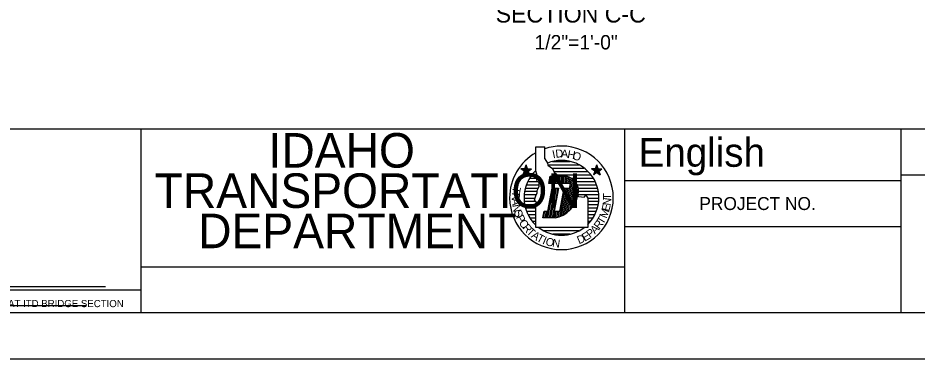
# Model space of a CAD drawing. Extents: x 0 to 68, y 0 to 47.1.
# Drawn here: x 25.33 to 44.86, y 0 to 7.4 of the extents above; entities that cross this region are included whole.
import ezdxf

# ---------------------------------------------------------------- set-up
doc = ezdxf.new("R2010")
doc.units = 0
for name, color, linetype in [('BORDER_ANNO_Cutsheet', 7, 'Continuous'), ('BRDG_ANNO_Anno-Large-Print', 7, 'Continuous'), ('BRDG_ANNO_Anno-Sheet', 7, 'Continuous'), ('BRDG_ANNO_Anno-Small-Print', 7, 'Continuous'), ('BRDG_ANNO_General-Notes', 7, 'Continuous')]:
    doc.layers.add(name, color=color, linetype=linetype)

msp = doc.modelspace()

# ---------------------------------------------------------------- linework, layer by layer
at = {"layer": 'BORDER_ANNO_Cutsheet'}
msp.add_lwpolyline([(0, 44), (68, 44), (68, 0), (0, 0)], close=True, dxfattribs=at)
at = {"layer": 'BRDG_ANNO_Anno-Large-Print'}
msp.add_line((23.799, 1.161), (26.811, 1.161), dxfattribs=at)
at = {"layer": 'BRDG_ANNO_Anno-Sheet'}
for p, q in [((3, 5), (38.5, 5)), ((28, 1), (28, 5)), ((38.5, 1), (38.5, 5)), ((38.5, 5), (67, 5)), ((44.5, 1), (44.5, 5)), ((36.569, 4.085), (36.569, 4.606)), ((36.569, 4.606), (36.766, 4.606)), ((36.766, 4.346), (36.766, 4.606)), ((36.766, 4.346), (36.819, 4.252)), ((36.402, 4.08), (36.245, 4.131)), ((36.331, 4.131), (36.245, 4.131)), ((36.315, 4.08), (36.245, 4.131)), ((36.386, 4.131), (36.288, 3.996)), ((36.315, 4.08), (36.474, 4.131)), ((36.331, 4.131), (36.359, 4.214)), ((36.331, 4.131), (36.43, 3.996)), ((36.359, 4.047), (36.359, 4.214)), ((36.386, 4.131), (36.359, 4.214)), ((36.386, 4.131), (36.474, 4.131)), ((36.402, 4.08), (36.474, 4.131)), ((36.819, 4.252), (36.829, 4.21)), ((36.829, 4.21), (36.932, 4.138)), ((36.834, 4.216), (37.501, 4.216)), ((36.93, 4.289), (37.316, 4.289)), ((36.93, 4.145), (37.614, 4.145)), ((36.932, 4.138), (36.965, 4.054)), ((37.935, 4.08), (37.776, 4.131)), ((37.847, 4.08), (37.776, 4.131)), ((37.864, 4.131), (37.776, 4.131)), ((37.919, 4.131), (37.82, 3.996)), ((37.847, 4.08), (38.005, 4.131)), ((37.864, 4.131), (37.891, 4.214)), ((37.864, 4.131), (37.962, 3.996)), ((37.891, 4.047), (37.891, 4.214)), ((37.919, 4.131), (37.891, 4.214)), ((37.919, 4.131), (38.005, 4.131)), ((37.935, 4.08), (38.005, 4.131)), ((36.315, 4.08), (36.288, 3.996)), ((36.359, 4.047), (36.288, 3.996)), ((36.359, 4.047), (36.43, 3.996)), ((36.402, 4.08), (36.43, 3.996)), ((36.434, 3.929), (36.585, 3.929)), ((36.484, 4.001), (36.587, 4.001)), ((36.549, 4.072), (36.572, 4.072)), ((36.589, 4.013), (36.569, 4.085)), ((36.589, 3.95), (36.589, 4.013)), ((36.589, 3.897), (36.589, 3.95)), ((36.85, 3.814), (36.881, 3.971)), ((36.879, 3.814), (36.907, 3.971)), ((36.881, 3.971), (37.225, 3.971)), ((36.91, 3.814), (36.94, 3.971)), ((36.942, 3.814), (36.971, 3.971)), ((36.957, 4.072), (37.701, 4.072)), ((36.965, 4.054), (37.069, 3.971)), ((36.974, 3.814), (37.004, 3.971)), ((37.005, 3.814), (37.035, 3.971)), ((37.031, 4.001), (37.765, 4.001)), ((37.038, 3.814), (37.066, 3.971)), ((37.069, 3.814), (37.099, 3.971)), ((37.101, 3.814), (37.13, 3.971)), ((37.133, 3.814), (37.163, 3.971)), ((37.165, 3.814), (37.194, 3.971)), ((37.196, 3.814), (37.226, 3.971)), ((37.199, 3.149), (37.344, 3.924)), ((37.227, 3.814), (37.256, 3.962)), ((37.26, 3.814), (37.286, 3.954)), ((37.291, 3.814), (37.315, 3.94)), ((37.337, 3.929), (37.815, 3.929)), ((37.847, 4.08), (37.82, 3.996)), ((37.891, 4.047), (37.82, 3.996)), ((37.891, 4.047), (37.962, 3.996)), ((37.935, 4.08), (37.962, 3.996)), ((44.5, 4), (60.5, 4)), ((36.341, 3.712), (36.623, 3.712)), ((36.362, 3.785), (36.637, 3.785)), ((36.394, 3.856), (36.596, 3.856)), ((36.6, 3.856), (36.589, 3.897)), ((36.641, 3.835), (36.6, 3.856)), ((36.62, 3.7), (36.641, 3.751)), ((36.641, 3.782), (36.641, 3.835)), ((36.641, 3.751), (36.641, 3.782)), ((37.322, 3.814), (36.85, 3.814)), ((37.235, 3.171), (37.373, 3.904)), ((37.273, 3.201), (37.399, 3.877)), ((37.304, 3.71), (37.322, 3.814)), ((37.311, 3.237), (37.425, 3.849)), ((37.351, 3.28), (37.45, 3.812)), ((37.394, 3.337), (37.474, 3.764)), ((37.42, 3.856), (37.855, 3.856)), ((37.465, 3.785), (37.886, 3.785)), ((37.489, 3.712), (37.909, 3.712)), ((38.5, 3.875), (44.5, 3.875)), ((36.315, 3.569), (36.581, 3.569)), ((36.325, 3.641), (36.596, 3.641)), ((36.557, 3.501), (36.569, 3.544)), ((36.569, 3.544), (36.6, 3.606)), ((36.6, 3.657), (36.62, 3.7)), ((36.6, 3.606), (36.6, 3.657)), ((36.829, 3.21), (36.922, 3.71)), ((36.832, 3.064), (36.954, 3.71)), ((36.865, 3.064), (36.986, 3.71)), ((36.896, 3.064), (37.017, 3.71)), ((36.922, 3.71), (37.06, 3.71)), ((36.929, 3.064), (37.05, 3.71)), ((37.06, 3.71), (36.966, 3.21)), ((37.087, 3.21), (37.181, 3.71)), ((37.094, 3.095), (37.209, 3.71)), ((37.127, 3.11), (37.24, 3.71)), ((37.163, 3.126), (37.273, 3.71)), ((37.181, 3.71), (37.304, 3.71)), ((37.444, 3.435), (37.491, 3.69)), ((37.481, 3.555), (37.496, 3.532)), ((37.485, 3.569), (37.935, 3.569)), ((37.495, 3.641), (37.925, 3.641)), ((37.496, 3.532), (37.559, 3.522)), ((37.559, 3.522), (37.621, 3.512)), ((37.621, 3.512), (37.652, 3.554)), ((37.652, 3.554), (37.694, 3.491)), ((36.312, 3.496), (36.555, 3.496)), ((36.316, 3.425), (36.562, 3.425)), ((36.326, 3.353), (36.596, 3.353)), ((36.538, 3.45), (36.557, 3.501)), ((36.569, 3.419), (36.538, 3.45)), ((36.589, 3.387), (36.569, 3.419)), ((36.569, 3.304), (36.6, 3.335)), ((36.6, 3.366), (36.589, 3.387)), ((36.6, 3.335), (36.6, 3.366)), ((37.69, 3.496), (37.938, 3.496)), ((37.694, 3.491), (37.694, 2.855)), ((37.694, 3.353), (37.924, 3.353)), ((37.695, 3.425), (37.934, 3.425)), ((36.343, 3.281), (36.567, 3.281)), ((36.367, 3.209), (36.565, 3.209)), ((36.399, 3.136), (36.565, 3.136)), ((36.569, 2.855), (36.569, 3.304)), ((36.719, 3.064), (36.746, 3.21)), ((36.737, 3.064), (36.765, 3.21)), ((36.746, 3.21), (36.829, 3.21)), ((36.77, 3.064), (36.797, 3.21)), ((36.801, 3.064), (36.829, 3.21)), ((36.96, 3.064), (36.987, 3.21)), ((36.966, 3.21), (37.087, 3.21)), ((36.992, 3.065), (37.02, 3.21)), ((37.026, 3.074), (37.051, 3.21)), ((37.06, 3.084), (37.082, 3.21)), ((37.694, 3.281), (37.907, 3.281)), ((37.694, 3.209), (37.883, 3.209)), ((37.694, 3.136), (37.85, 3.136)), ((36.44, 3.065), (36.566, 3.065)), ((36.491, 2.992), (36.565, 2.992)), ((36.985, 3.064), (36.719, 3.064)), ((37.694, 3.065), (37.81, 3.065)), ((37.694, 2.992), (37.76, 2.992)), ((36.555, 2.921), (36.567, 2.921)), ((37.694, 2.855), (36.569, 2.855)), ((37.501, 2.782), (36.744, 2.782)), ((38.5, 2.875), (44.5, 2.875)), ((37.317, 2.711), (36.935, 2.711)), ((28, 2), (38.5, 2))]:
    msp.add_line(p, q, dxfattribs=at)
msp.add_lwpolyline([(3, 43), (67, 43), (67, 1), (3, 1)], close=True, dxfattribs=at)
for centre, radius, start, end in [((37.125, 3.5), 1.125, 90, 108.596), ((37.125, 3.5), 1.125, 0, 90), ((37.125, 3.5), 1.125, 119.6331, 180), ((37.125, 3.5), 0.813, 90, 112.1452), ((37.125, 3.5), 0.813, 0, 90), ((37.125, 3.5), 0.813, 133.1926, 180), ((37.167, 3.648), 0.328, 343.4981, 79.7362), ((36.87, 3.676), 0.623, 280.6479, 348.7719), ((37.125, 3.5), 1.125, 180, 270), ((37.125, 3.5), 0.813, 180.2644, 226.7946), ((37.125, 3.5), 1.125, 270, 0), ((37.125, 3.5), 0.813, 314.427, 0), ((37.125, 3.5), 0.813, 232.5658, 270), ((37.125, 3.5), 0.813, 270, 307.4536)]:
    msp.add_arc(centre, radius, start, end, dxfattribs=at)
at = {"layer": 'BRDG_ANNO_Anno-Small-Print'}
for p, q in [((24.432, 1.573), (27.227, 1.573)), ((23, 1.5), (28, 1.5))]:
    msp.add_line(p, q, dxfattribs=at)

# ---------------------------------------------------------------- texts
at = {"layer": 'BRDG_ANNO_Anno-Sheet'}
for s, height, p in [('IDAHO', 0.75, (30.767, 4.156)), ('English', 0.625, (38.801, 4.174)), ('TRANSPORTATION', 0.75, (28.294, 3.281)), ('PROJECT NO.', 0.28125, (40.118, 3.235)), ('DEPARTMENT', 0.75, (29.239, 2.406))]:
    msp.add_text(s, height=height, dxfattribs=at).set_placement(p)
for s, rotation, p in [('I', 11.9519, (36.944, 4.356)), ('D', 5.2118, (37.002, 4.369)), ('A', 357.8718, (37.114, 4.376)), ('H', 349.6318, (37.244, 4.367)), ('O', 342.1917, (37.349, 4.346)), ('T', 259.4265, (36.076, 3.751)), ('R', 266.0275, (36.053, 3.615)), ('T', 90.4926, (38.204, 3.459)), ('A', 273.764, (36.046, 3.481)), ('N', 280.3758, (36.057, 3.342)), ('E', 75.6105, (38.159, 3.194)), ('N', 83.1932, (38.19, 3.326)), ('S', 287.9279, (36.086, 3.208)), ('P', 295.4976, (36.131, 3.081)), ('M', 67.7139, (38.101, 3.041)), ('O', 302.6446, (36.191, 2.96)), ('R', 309.9079, (36.267, 2.845)), ('R', 52.3344, (37.947, 2.802)), ('T', 59.0362, (38.027, 2.91)), ('T', 317.1211, (36.355, 2.742)), ('A', 324.6375, (36.456, 2.651)), ('E', 30.5476, (37.631, 2.547)), ('P', 37.6656, (37.746, 2.619)), ('A', 45, (37.851, 2.701)), ('T', 331.7503, (36.569, 2.574)), ('I', 337.0213, (36.699, 2.507)), ('O', 343.3287, (36.765, 2.481)), ('N', 351.6598, (36.917, 2.44)), ('D', 22.9887, (37.506, 2.491))]:
    msp.add_text(s, height=0.174, rotation=rotation, dxfattribs=at).set_placement(p)
at = {"layer": 'BRDG_ANNO_Anno-Small-Print'}
msp.add_text('ORIGINAL STORED AT ITD BRIDGE SECTION', height=0.15643, dxfattribs=at).set_placement((23.125, 1.126))
at = {"layer": 'BRDG_ANNO_General-Notes'}
for s, height, p in [('SECTION C-C', 0.375, (35.697, 7.306)), ('1/2"=1\'-0"', 0.3125, (36.541, 6.722))]:
    msp.add_text(s, height=height, dxfattribs=at).set_placement(p)

doc.saveas('drawing.dxf')
